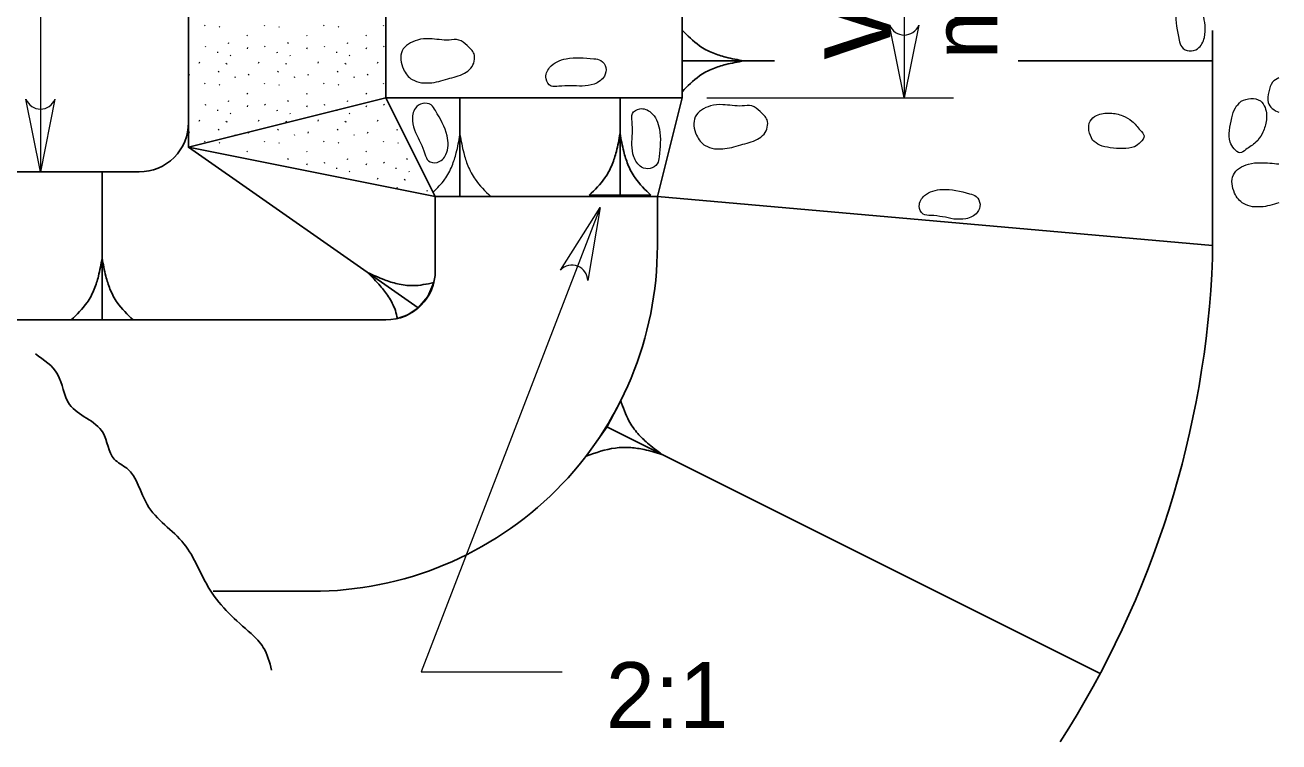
# Model space of a CAD drawing. Extents: x 1043.1 to 1101.1, y 672.4 to 716.4.
# Drawn here: x 1060.033 to 1063.081, y 702.445 to 704.187 of the extents above; entities that cross this region are included whole.
import ezdxf

# ---------------------------------------------------------------- set-up
doc = ezdxf.new("R2010")
doc.units = 0
doc.header["$LTSCALE"] = 0.064
doc.layers.add('1', color=7, linetype='Continuous', lineweight=13)

msp = doc.modelspace()

# ---------------------------------------------------------------- linework, layer by layer
at = {"layer": '1'}
for p, q in [((1062.16983, 704.7295), (1062.16983, 704.00992)), ((1060.46983, 704.18683), (1060.471, 704.185)), ((1060.5055, 704.1835), (1060.50675, 704.18175)), ((1060.61433, 704.18683), (1060.6155, 704.185)), ((1060.65, 704.1835), (1060.65125, 704.18175)), ((1060.759, 704.18683), (1060.76025, 704.185)), ((1060.79458, 704.1835), (1060.79592, 704.18175)), ((1060.9035, 704.18683), (1060.90475, 704.185)), ((1060.52783, 704.14192), (1060.529, 704.14458)), ((1060.57275, 704.16208), (1060.57392, 704.16033)), ((1060.67233, 704.14192), (1060.6735, 704.14458)), ((1060.71725, 704.16208), (1060.71842, 704.16033)), ((1060.81683, 704.14192), (1060.818, 704.14458)), ((1060.86175, 704.16208), (1060.86292, 704.16033)), ((1060.47092, 704.13542), (1060.47208, 704.13358)), ((1060.50083, 704.12192), (1060.50108, 704.11925)), ((1060.53225, 704.11392), (1060.53342, 704.11208)), ((1060.57375, 704.1295), (1060.57492, 704.13225)), ((1060.6155, 704.13542), (1060.61675, 704.13358)), ((1060.64542, 704.12192), (1060.64575, 704.11925)), ((1060.67675, 704.11392), (1060.67792, 704.11208)), ((1060.71825, 704.1295), (1060.71942, 704.13225)), ((1060.76008, 704.13542), (1060.76133, 704.13358)), ((1060.79, 704.12192), (1060.79033, 704.11925)), ((1060.82125, 704.11392), (1060.82242, 704.11208)), ((1060.86275, 704.1295), (1060.86392, 704.13225)), ((1060.90458, 704.13542), (1060.90583, 704.13358)), ((1060.4565, 704.0945), (1060.45775, 704.09725)), ((1060.52142, 704.0945), (1060.52258, 704.09275)), ((1060.52258, 704.09383), (1060.52392, 704.092)), ((1060.601, 704.0945), (1060.60233, 704.09725)), ((1060.666, 704.0945), (1060.66725, 704.09275)), ((1060.66725, 704.09383), (1060.66842, 704.092)), ((1060.74575, 704.0945), (1060.74692, 704.09725)), ((1060.8105, 704.0945), (1060.81175, 704.09275)), ((1060.81175, 704.09383), (1060.81292, 704.092)), ((1060.89025, 704.0945), (1060.89142, 704.09725)), ((1062.91942, 704.09992), (1062.59458, 704.09992)), ((1062.91942, 704.09992), (1062.59458, 704.09992)), ((1060.43208, 704.06525), (1060.43333, 704.06792)), ((1060.50358, 704.07208), (1060.50483, 704.07483)), ((1060.54292, 704.06158), (1060.54408, 704.05983)), ((1060.57675, 704.06525), (1060.57792, 704.06792)), ((1060.64808, 704.07208), (1060.64942, 704.07483)), ((1060.68742, 704.06158), (1060.68858, 704.05983)), ((1060.72125, 704.06525), (1060.72242, 704.06792)), ((1060.79283, 704.07208), (1060.794, 704.07483)), ((1060.832, 704.06158), (1060.83325, 704.05983)), ((1060.86575, 704.06525), (1060.867, 704.06792)), ((1060.46983, 704.04592), (1060.471, 704.044)), ((1060.5055, 704.04258), (1060.50675, 704.04083)), ((1060.57275, 704.02108), (1060.57392, 704.01933)), ((1060.61433, 704.04592), (1060.6155, 704.044)), ((1060.65, 704.04258), (1060.65125, 704.04083)), ((1060.71725, 704.02108), (1060.71842, 704.01933)), ((1060.759, 704.04592), (1060.76025, 704.044)), ((1060.79458, 704.04258), (1060.79592, 704.04083)), ((1060.86175, 704.02108), (1060.86292, 704.01933)), ((1060.9035, 704.04592), (1060.90475, 704.044)), ((1060.47092, 703.99433), (1060.47208, 703.9925)), ((1060.52783, 704.00092), (1060.529, 704.00358)), ((1060.57375, 703.9885), (1060.57492, 703.99125)), ((1060.6155, 703.99433), (1060.61675, 703.9925)), ((1060.67233, 704.00092), (1060.6735, 704.00358)), ((1060.71825, 703.9885), (1060.71942, 703.99125)), ((1060.76008, 703.99433), (1060.76133, 703.9925)), ((1060.81683, 704.00092), (1060.818, 704.00358)), ((1060.86275, 703.9885), (1060.86392, 703.99125)), ((1060.90458, 703.99433), (1060.90583, 703.9925)), ((1061.69, 704.00992), (1062.28975, 704.00992)), ((1060.50083, 703.981), (1060.50108, 703.97833)), ((1060.53225, 703.973), (1060.53342, 703.97125)), ((1060.64542, 703.981), (1060.64575, 703.97833)), ((1060.67675, 703.973), (1060.67792, 703.97125)), ((1060.79, 703.981), (1060.79033, 703.97833)), ((1060.82125, 703.973), (1060.82242, 703.97125)), ((1060.4565, 703.95358), (1060.45775, 703.95633)), ((1060.50358, 703.93125), (1060.50483, 703.93392)), ((1060.52142, 703.95358), (1060.52258, 703.95183)), ((1060.52258, 703.95292), (1060.52392, 703.95108)), ((1060.601, 703.95358), (1060.60233, 703.95633)), ((1060.64808, 703.93125), (1060.64942, 703.93392)), ((1060.666, 703.95358), (1060.66725, 703.95183)), ((1060.66725, 703.95292), (1060.66842, 703.95108)), ((1060.74575, 703.95358), (1060.74692, 703.95633)), ((1060.79283, 703.93125), (1060.794, 703.93392)), ((1060.8105, 703.95358), (1060.81175, 703.95183)), ((1060.81175, 703.95292), (1060.81292, 703.95108)), ((1060.89025, 703.95358), (1060.89142, 703.95633)), ((1060.93733, 703.93125), (1060.9385, 703.93392)), ((1060.43208, 703.92425), (1060.43333, 703.927)), ((1060.46983, 703.90492), (1060.471, 703.90308)), ((1060.5055, 703.90158), (1060.50675, 703.89983)), ((1060.54292, 703.92075), (1060.54408, 703.91892)), ((1060.57675, 703.92425), (1060.57792, 703.927)), ((1060.61433, 703.90492), (1060.6155, 703.90308)), ((1060.65, 703.90158), (1060.65125, 703.89983)), ((1060.68742, 703.92075), (1060.68858, 703.91892)), ((1060.72125, 703.92425), (1060.72242, 703.927)), ((1060.759, 703.90492), (1060.76025, 703.90308)), ((1060.79458, 703.90158), (1060.79592, 703.89983)), ((1060.832, 703.92075), (1060.83325, 703.91892)), ((1060.86575, 703.92425), (1060.867, 703.927)), ((1060.9035, 703.90492), (1060.90475, 703.90308)), ((1060.93925, 703.90158), (1060.94042, 703.89983)), ((1060.57275, 703.88025), (1060.57392, 703.87842)), ((1060.71725, 703.88025), (1060.71842, 703.87842)), ((1060.86175, 703.88025), (1060.86292, 703.87842)), ((1060.6155, 703.85342), (1060.61583, 703.85292)), ((1060.67233, 703.85992), (1060.6735, 703.86258)), ((1060.71825, 703.8475), (1060.71942, 703.85033)), ((1060.76008, 703.85342), (1060.76133, 703.85158)), ((1060.79, 703.84), (1060.79033, 703.83725)), ((1060.81683, 703.85992), (1060.818, 703.86258)), ((1060.86275, 703.8475), (1060.86392, 703.85033)), ((1060.90458, 703.85342), (1060.90583, 703.85158)), ((1060.9345, 703.84), (1060.93483, 703.83725)), ((1060.9615, 703.85992), (1060.96275, 703.86258)), ((1060.82125, 703.832), (1060.82242, 703.83008)), ((1060.89025, 703.81258), (1060.89142, 703.81525)), ((1060.95508, 703.81258), (1060.95633, 703.81083)), ((1060.95633, 703.81192), (1060.9575, 703.81008)), ((1060.96592, 703.832), (1060.96708, 703.83008)), ((1060.93733, 703.79025), (1060.9385, 703.793)), ((1061.01042, 703.78333), (1061.0115, 703.786))]:
    msp.add_line(p, q, dxfattribs=at)
at = {"layer": '1', "lineweight": 25}
for p, q in [((1061.63, 704.02492), (1061.63, 704.17483)), ((1062.91942, 704.174), (1062.91942, 704.09992)), ((1061.63, 704.09992), (1061.85442, 704.09992)), ((1062.447, 704.09992), (1062.91942, 704.09992)), ((1062.91942, 703.62025), (1062.91942, 704.09992)), ((1060.43058, 703.89), (1060.91042, 704.00992)), ((1060.91042, 704.00992), (1061.63, 704.00992)), ((1061.09033, 704.00992), (1061.09033, 703.77)), ((1061.47933, 704.01092), (1061.47933, 703.77325)), ((1060.43058, 703.89), (1060.98883, 703.49933)), ((1058.45158, 703.83), (1060.31075, 703.83)), ((1060.22075, 703.47033), (1060.22075, 703.83)), ((1061.03033, 703.77008), (1061.03033, 703.59025)), ((1061.55433, 703.77325), (1061.40433, 703.77325)), ((1061.57008, 703.77008), (1061.57008, 703.65025)), ((1061.57008, 703.77008), (1062.91883, 703.65133)), ((1060.29575, 703.47033), (1060.14583, 703.47033)), ((1062.64625, 702.611), (1061.44683, 703.21058)), ((1060.7305, 702.81075), (1060.49058, 702.81075))]:
    msp.add_line(p, q, dxfattribs=at)
at = {"layer": '1'}
for points in [[(1060.07083, 705.02933), (1060.07083, 704.30983), (1060.07083, 703.83)], [(1062.20517, 704.1865), (1062.16983, 704.00992), (1062.1345, 704.1865), (1062.13467, 704.1865)], [(1060.10617, 704.00658), (1060.07083, 703.83), (1060.0355, 704.00658), (1060.03567, 704.00658)], [(1061.16533, 703.77), (1061.03, 703.77025), (1061.02508, 703.78083)], [(1061.43125, 703.74342), (1060.99633, 702.61508), (1061.33858, 702.61508)], [(1061.33492, 703.59142), (1061.43125, 703.74342), (1061.40075, 703.566), (1061.40067, 703.56608)]]:
    msp.add_lwpolyline(points, dxfattribs=at)
at = {"layer": '1', "lineweight": 25}
for points in [[(1060.43058, 704.96942), (1060.43058, 704.90942), (1060.43058, 703.95), (1060.43058, 703.89), (1061.03033, 703.77008)], [(1061.03033, 703.77008), (1060.91042, 704.00992), (1060.91042, 704.7295), (1061.03033, 704.96942)], [(1061.57008, 704.96942), (1061.63, 704.7295), (1061.63, 704.00992), (1061.57008, 703.77008)], [(1061.57008, 703.77008), (1061.39808, 703.77008), (1061.03033, 703.77008)], [(1060.93825, 703.47408), (1060.96383, 703.48283), (1060.989, 703.49925), (1061.0125, 703.527), (1061.0265, 703.56083)], [(1060.91042, 703.47033), (1059.41108, 703.47033), (1057.91192, 703.47033)], [(1061.39708, 703.13925), (1061.44683, 703.20992), (1061.48108, 703.27442)]]:
    msp.add_lwpolyline(points, dxfattribs=at)
at = {"layer": '1'}
for centre, start, end in [((1062.16992, 704.20081), 202.08789, 337.91402), ((1060.07092, 704.02089), 202.08789, 337.91402), ((1061.36258, 703.56535), 1.00871, 136.83483)]:
    msp.add_arc(centre, 0.03811, start, end, dxfattribs=at)
at = {"layer": '1', "lineweight": 25}
for centre, major_axis, start_param, end_param in [((1060.31071, 703.94999), (-0.11994, 0), 1.5707963, 3.1415927), ((1060.7305, 703.65017), (-0.83958, 0), 1.5707963, 3.1415927), ((1060.5765, 703.71267), (2.34474, 0), 5.7116877, 6.2437295), ((1060.91041, 703.5902), (0.11994, 0), 4.712389, 6.2831853)]:
    msp.add_ellipse(centre, major_axis=major_axis, ratio=0.999895, start_param=start_param, end_param=end_param, dxfattribs=at)
at = {"layer": '1'}
for points in [[(1062.90142, 704.186), (1062.89933, 704.15642), (1062.88283, 704.1295), (1062.8625, 704.12392), (1062.84433, 704.13375), (1062.83825, 704.15033), (1062.83075, 704.21733), (1062.84733, 704.25942), (1062.87358, 704.27108), (1062.8925, 704.26092), (1062.89525, 704.24225), (1062.90142, 704.186)], [(1060.9965, 704.04675), (1060.97442, 704.05433), (1060.95308, 704.07992), (1060.94992, 704.124), (1060.98675, 704.1505), (1061.01675, 704.15358), (1061.06392, 704.1505), (1061.08742, 704.1505), (1061.10775, 704.13692), (1061.1245, 704.11675), (1061.11708, 704.08233), (1061.101, 704.06975), (1061.06042, 704.05608), (1061.01675, 704.04633), (1060.9965, 704.04675)], [(1061.38733, 704.03808), (1061.41633, 704.0435), (1061.44125, 704.06292), (1061.44458, 704.08375), (1061.43283, 704.10075), (1061.41558, 704.10492), (1061.34833, 704.10492), (1061.30825, 704.08375), (1061.2995, 704.05633), (1061.31175, 704.03875), (1061.33075, 704.03808), (1061.38733, 704.03808)], [(1063.0805, 704.05892), (1063.06475, 704.04775), (1063.05608, 704.02475), (1063.05425, 703.9985), (1063.08025, 703.97492), (1063.0805, 703.97483)], [(1060.98192, 703.92542), (1060.97483, 703.95408), (1060.98225, 703.98475), (1060.99975, 703.99642), (1061.02, 703.99275), (1061.03092, 703.97883), (1061.05883, 703.9175), (1061.05608, 703.87225), (1061.03483, 703.853), (1061.01383, 703.85683), (1061.00533, 703.87383), (1060.98192, 703.92542)], [(1061.7085, 703.88642), (1061.6865, 703.89392), (1061.66525, 703.9195), (1061.662, 703.96358), (1061.69883, 703.99025), (1061.72883, 703.99333), (1061.776, 703.99025), (1061.7995, 703.99025), (1061.81983, 703.9765), (1061.83658, 703.95633), (1061.82925, 703.92192), (1061.81308, 703.90933), (1061.7725, 703.89575), (1061.72883, 703.886), (1061.7085, 703.88642)], [(1062.9885, 704.00183), (1062.97475, 703.98592), (1062.96583, 703.96108), (1062.96042, 703.93058), (1062.962, 703.90258), (1062.97133, 703.88642), (1062.98583, 703.8765), (1063.00025, 703.88425), (1063.02458, 703.90208), (1063.03958, 703.92275), (1063.04933, 703.95233), (1063.04692, 703.98625), (1063.03533, 704.0025), (1063.01242, 704.00825), (1062.9885, 704.00183)], [(1061.50775, 703.896), (1061.51275, 703.86692), (1061.53175, 703.84175), (1061.5525, 703.838), (1061.56975, 703.8495), (1061.57408, 703.86658), (1061.57508, 703.93408), (1061.55442, 703.9745), (1061.52725, 703.98342), (1061.50942, 703.97158), (1061.5085, 703.95258), (1061.50775, 703.896)], [(1062.62775, 703.90708), (1062.64492, 703.89508), (1062.67058, 703.88883), (1062.7015, 703.88658), (1062.72925, 703.89125), (1062.74442, 703.90208), (1062.75275, 703.9175), (1062.7435, 703.93108), (1062.72325, 703.9535), (1062.70108, 703.96633), (1062.67075, 703.97292), (1062.63708, 703.967), (1062.62208, 703.95358), (1062.61883, 703.93025), (1062.62775, 703.90708)], [(1061.02508, 703.78083), (1061.0535, 703.81208), (1061.07125, 703.845), (1061.08133, 703.87633), (1061.09033, 703.91992)], [(1061.09033, 703.91992), (1061.09933, 703.87633), (1061.10942, 703.845), (1061.12708, 703.81208), (1061.16533, 703.77)], [(1063.01633, 703.74533), (1062.99425, 703.75292), (1062.97292, 703.7785), (1062.96975, 703.8225), (1063.0065, 703.84908), (1063.0365, 703.85225), (1063.0805, 703.84933)], [(1062.29033, 703.71533), (1062.31992, 703.71608), (1062.3475, 703.73142), (1062.35408, 703.75142), (1062.34508, 703.77), (1062.32883, 703.77683), (1062.26225, 703.78733), (1062.21933, 703.77258), (1062.2065, 703.74692), (1062.21583, 703.72758), (1062.23442, 703.72408), (1062.29033, 703.71533)], [(1063.0805, 703.75483), (1063.08025, 703.75475), (1063.0365, 703.74492), (1063.01633, 703.74533)]]:
    msp.add_spline(points, degree=3, dxfattribs=at)
at = {"layer": '1', "lineweight": 25}
for points in [[(1061.63, 704.17483), (1061.67208, 704.13675), (1061.70508, 704.119), (1061.73642, 704.10892), (1061.78, 704.09992)], [(1061.78, 704.09992), (1061.73642, 704.09092), (1061.70508, 704.08083), (1061.67208, 704.06308), (1061.63, 704.02492)], [(1061.40433, 703.77325), (1061.4425, 703.81525), (1061.46025, 703.84825), (1061.47033, 703.8795), (1061.47933, 703.92308)], [(1061.47933, 703.92308), (1061.48833, 703.8795), (1061.49842, 703.84825), (1061.51608, 703.81525), (1061.55433, 703.77325)], [(1060.14583, 703.47033), (1060.184, 703.51233), (1060.20158, 703.54533), (1060.21175, 703.57658), (1060.22075, 703.62025)], [(1060.22075, 703.62025), (1060.22975, 703.57658), (1060.23983, 703.54533), (1060.2575, 703.51233), (1060.29575, 703.47033)], [(1061.02692, 703.56092), (1060.97542, 703.55358), (1060.93825, 703.558), (1060.90683, 703.56775), (1060.86592, 703.58533)], [(1060.86592, 703.58533), (1060.8965, 703.55292), (1060.91633, 703.52675), (1060.93325, 703.49333), (1060.93825, 703.47408)], [(1060.05858, 703.38758), (1060.11233, 703.33808), (1060.14142, 703.265), (1060.22283, 703.19608), (1060.25, 703.132), (1060.2805, 703.10958), (1060.33008, 703.0215), (1060.41958, 702.92633), (1060.48292, 702.81375), (1060.58292, 702.70783)], [(1061.48108, 703.27442), (1061.50092, 703.22475), (1061.5225, 703.19408), (1061.546, 703.17108), (1061.581, 703.1435)], [(1061.581, 703.1435), (1061.53792, 703.155), (1061.50542, 703.15992), (1061.468, 703.15892), (1061.39708, 703.13925)], [(1060.58292, 702.70783), (1060.61233, 702.67433), (1060.6325, 702.61858)]]:
    msp.add_spline(points, degree=3, dxfattribs=at)

# ---------------------------------------------------------------- texts
at = {"layer": '1'}
for s, width, p in [('W/4', 1.25, (1062.13583, 704.1025)), ('min.', 1.05, (1062.39583, 704.1025))]:
    msp.add_text(s, height=0.16, rotation=90, dxfattribs=dict(at, width=width)).set_placement(p)
msp.add_text('2:1', height=0.16, dxfattribs=at).set_placement((1061.445, 702.47842))

doc.saveas('drawing.dxf')
